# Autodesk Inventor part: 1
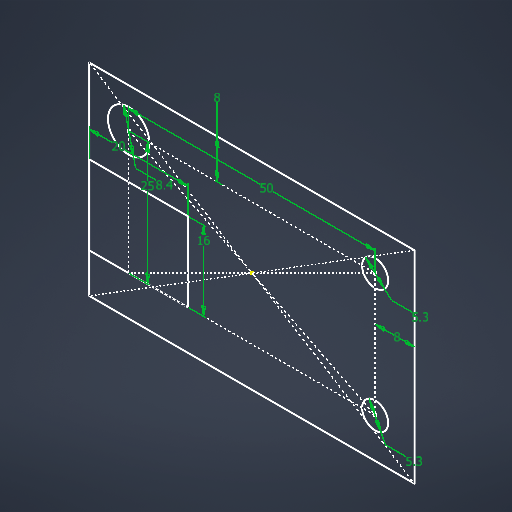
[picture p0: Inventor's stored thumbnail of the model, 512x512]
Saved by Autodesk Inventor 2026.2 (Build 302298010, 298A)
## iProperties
Created: 2026-04
Part Number: 1
Material: 일반
Document SubType Name: Modeling
Designer: work
Density: 1 g/cm^3
Appearance: 기본값
Author: work
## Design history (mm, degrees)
sketch "스케치1"
  geometry: L1 (-25, -12.5)-(25, -12.5); L2 (25, -12.5)-(25, 12.5); L3 (25, 12.5)-(-25, 12.5); L4 (-25, 12.5)-(-25, -12.5); L5 (-25, -12.5)-(25, 12.5); L6 (25, -12.5)-(-25, 12.5); L7 (33, -20.5)-(-33, -20.5); L8 (-33, -20.5)-(-33, 20.5); L9 (-33, 20.5)-(33, 20.5); L10 (33, 20.5)-(33, -20.5); L11 (33, -20.5)-(-33, 20.5); L12 (-33, -20.5)-(33, 20.5); L13 (-33, 3.5)-(-13, 3.5); L14 (-13, 3.5)-(-13, -12.5); L15 (-13, -12.5)-(-33, -12.5); L16 (-33, -12.5)-(-33, 3.5); C1 r 4.2 at (-25, 12.5); C2 r 2.65 at (25, 12.5); C3 r 2.65 at (25, -12.5); 1 further point
  constraints: 32 end point, 6 parallel, 4 midpoint, 3 centre point, 3 coincident, 3 horizontal, 3 perpendicular, 2 point on line
  dimensions: "d0" = 50 distance of L2.end L3.end; "d1" = 25 distance of L3.end L1.start; "d2" = 8.4 diameter of C1; "d3" = 5.3 diameter of C2; "d4" = 5.3 diameter of C3; "d5" = 8 distance between parallel lines of L9 L3; "d6" = 8 distance between parallel lines of L10 L2; "d7" = 20 distance of L13.start L13.end; "d8" = 16 distance of L13.end L14.end
